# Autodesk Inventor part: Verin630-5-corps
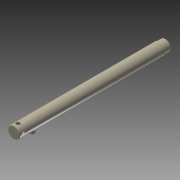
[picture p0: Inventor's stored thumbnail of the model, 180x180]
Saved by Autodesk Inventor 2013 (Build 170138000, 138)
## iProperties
Created: 2015-07
Part Number: Verin630-5-corps
Material: Générique
Document SubType Name: Modeling
Designer: OL
Density: 1 g/cm^3
Author: OL
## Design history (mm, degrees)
sketch "Esquisse1"
  geometry: L1 (-18, 0)-(88.903, 0); L2 (-18, 0)-(-18, 23); L3 (-18, 23)-(-16, 25); L4 (-16, 25)-(16, 25); L5 (16, 25)-(18, 23); L6 (18, 23)-(20, 25); L7 (20, 25)-(598, 25); L8 (18, 23)-(18, 0); L9 (18, 22)-(578, 22); L10 (598, 25)-(598, 23); L11 (598, 23)-(622, 23); L12 (622, 23)-(624, 21); L13 (624, 21)-(624, 18); L14 (627, 16)-(627, 15); L15 (627, 15)-(580, 15); L16 (580, 15)-(578, 17); L17 (578, 17)-(578, 22); L18 (624, 18)-(627, 16); A1 r 5.492 centre (18, 19.886) between (20, 25) and (16, 25); 1 further point
  constraints: 36 end point, 11 perpendicular, 3 point on line, 2 parallel, 2 point on circle, 1 centre point, 1 collinear, 1 horizontal
  dimensions: "d0" = 25 distance between parallel lines of L1 L4; "d2" = 18 distance from line of L2 point (0, 0); "d3" = 18 distance from line of L8 point (0, 0); "d4" = 2 horizontal distance of L4.end L5.end; "d5" = 2 horizontal distance of L4.end L5.end; "d6" = 23 distance of L1.start L2.end; "d7" = 22 distance between parallel lines of L1 L9; "d8" = 25 distance between parallel lines of L1 L7; "d9" = 624 distance from line of L13 point (0, 0); "d10" = 0 distance from line of L1 point (0, 0); "d11" = 560 distance between parallel lines of L17 L8; "d12" = 2 distance between parallel lines of L7 L11; "d13" = 2 horizontal distance of L11.end L12.end; "d14" = 15 distance between parallel lines of L1 L15; "d15" = 2 horizontal distance of L15.end L16.end; "d16" = 2 horizontal distance of L15.end L16.end; "d17" = 20 distance between parallel lines of L10 L17; "d18" = 3 horizontal distance of L13.end L14.start; "d19" = 7 distance from line of L7 L13.end; "d20" = 2 vertical distance of L13.end L14.start
revolve "Révolution1" sketch "Esquisse1" stored, may be unused: angle "d21" = 90 deg
sketch "Esquisse2"
  geometry: C1 r 8.1 at (0, 0); 1 further point
  constraints: 1 centre point, 1 coincident
  dimensions: "d22" = 16.2 diameter of C1
extrude "Extrusion1" cut sketch "Esquisse2" stored distance "d24" = 50; taper "d25" = 0 deg
sketch "Esquisse4"
  geometry: C1 r 8.363 at (0, 0); 1 further point
  constraints: 1 centre point, 1 coincident
extrude "Extrusion2" cut sketch "Esquisse4" stored distance "d36" = 2; taper "d37" = 0 deg
sketch "Esquisse5"
  geometry: L1 (47.5, -18.6)-(52.5, -18.6); L2 (52.5, -18.6)-(52.5, -36.6); L3 (52.5, -36.6)-(47.5, -36.6); L4 (47.5, -36.6)-(47.5, -18.6); L5 (60, -17.299)-(60, -65.647); L6 (0, -83.852)-(0, 43.582) reference; L7 (-147, 0)-(756, 0) reference; 1 further point
  constraints: 10 end point, 3 parallel, 1 horizontal, 1 perpendicular
  dimensions: "d38" = 60 distance between parallel lines of L5 L6; "d39" = 36.6 distance between parallel lines of L3 L7; "d40" = 12.5 distance between parallel lines of L4 L5; "d41" = 7.5 distance between parallel lines of L5 L2; "d42" = 18 distance of L3.end L1.start
revolve "Révolution3" sketch "Esquisse5" stored, may be unused: angle "d43" = 90 deg
fillet "Congé2" dims "d44" = 5
sketch "Esquisse6"
  geometry: C1 r 8 at (0, 0); 1 further point
  constraints: 1 centre point, 1 coincident
  dimensions: "d45" = 16 diameter of C1
extrude "Extrusion3" cut sketch "Esquisse6" stored distance "d47" = 50; taper "d48" = 0 deg
node "Solide1"
